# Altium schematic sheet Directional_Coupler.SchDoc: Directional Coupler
size A4; Author: Almela; Revision: 1.2; SheetNumber: 6; SheetTotal: 7
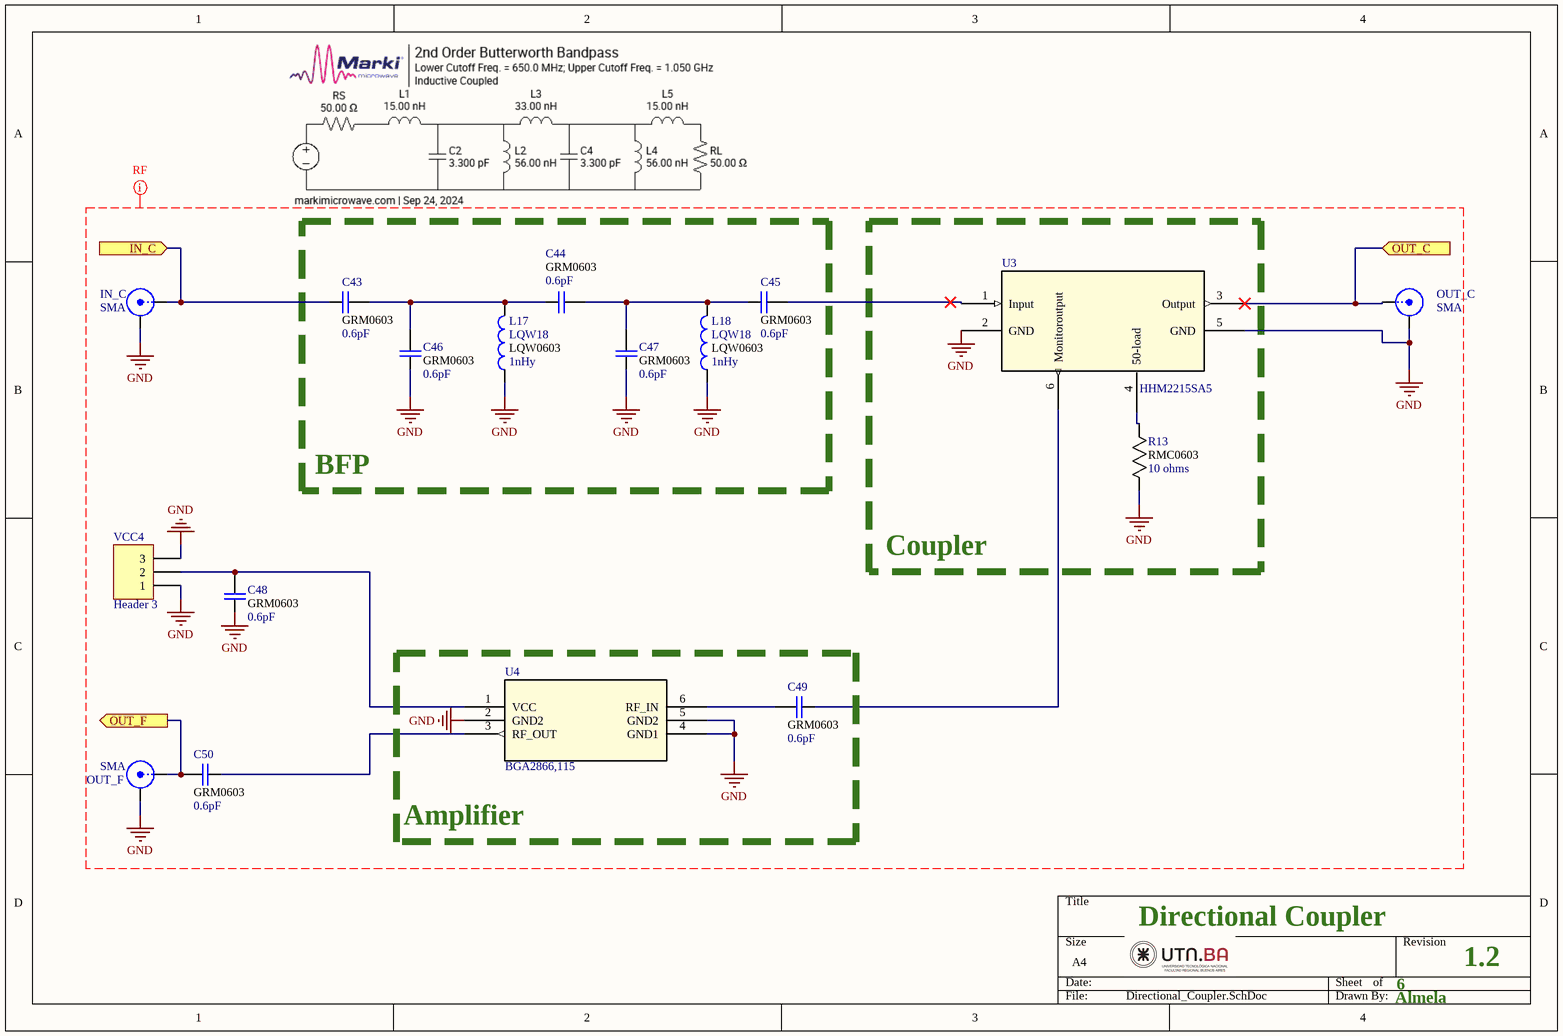
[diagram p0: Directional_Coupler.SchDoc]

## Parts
C43  value 0.6pF  footprint: GRM0603  [CAPC1608X90N]  (hidden comment: Cap 0603)
C44  value 0.6pF  footprint: GRM0603  [CAPC1608X90N]  (hidden comment: Cap 0603)
C45  value 0.6pF  footprint: GRM0603  [CAPC1608X90N]  (hidden comment: Cap 0603)
C46  value 0.6pF  footprint: GRM0603  [CAPC1608X90N]  (hidden comment: Cap 0603)
C47  value 0.6pF  footprint: GRM0603  [CAPC1608X90N]  (hidden comment: Cap 0603)
C48  value 0.6pF  footprint: GRM0603  [CAPC1608X90N]  (hidden comment: Cap 0603)
C49  value 0.6pF  footprint: GRM0603  [CAPC1608X90N]  (hidden comment: Cap 0603)
C50  value 0.6pF  footprint: GRM0603  [CAPC1608X90N]  (hidden comment: Cap 0603)
IN_C  SMA  [SMA-142-0701-851_V2]
L17  LQW18  value 1nHy  Parameter 1: LQW0603  [INDC1608X100N]
L18  LQW18  value 1nHy  Parameter 1: LQW0603  [INDC1608X100N]
OUT_C  SMA  [SMA-142-0701-851_V2]
OUT_F  SMA  [SMA-142-0701-851]
R13  value 10 ohms  footprint: RMC0603  [RESC1508X55N]  (hidden comment: Resistor)
U3  HHM2215SA5  [HHM-6_1P6X0P8]
U4  BGA2866,115  [SOT363_NXP]
VCC4  Header 3  [HDR1X3]

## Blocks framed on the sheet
BFP: C43-C47 L17 L18
Coupler: R13 U3
Amplifier: C49 U4

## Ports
IN_C (in), OUT_C (in), OUT_F (out)

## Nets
GND: C46.1 C47.1 C48.1 IN_C.2(Y) L17.1 L18.1 OUT_C.2(Y) OUT_F.2(Y) R13.1 U3.2(GND) U3.5(GND) U4.2(GND2) U4.4(GND1) U4.5(GND2) VCC4.1 VCC4.3
IN_C: C43.1 IN_C.1(X) ; port IN_C
OUT_C: OUT_C.1(X) U3.3(Output) ; port OUT_C
OUT_F: C50.2 OUT_F.1(X) ; port OUT_F
NetC43_2: C43.2 C44.1 C46.2 L17.2
NetC44_2: C44.2 C45.1 C47.2 L18.2
NetC45_2: C45.2 U3.1(Input)
NetC48_2: C48.2 U4.1(VCC) VCC4.2
NetC49_1: C49.1 U3.6(Monitoroutput)
NetC49_2: C49.2 U4.6(RF_IN)
NetC50_1: C50.1 U4.3(RF_OUT)
NetR13_2: R13.2 U3.4(50-load)

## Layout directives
net class RF50R: GND

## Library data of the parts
C43-C50 = Cap: Capacitor GRM18 0603
IN_C OUT_C = SMA: SMA Straight Connector
L17 L18 = LQW18: Ind RF Chip Wirewound 18nH 5% 100MHz 40Q-Factor 550mA 0603 Paper T/R; MP: LQW18AN18NJ00D
OUT_F = SMB: SMB Straight Connector
R13 = Resistor: Resistor RMC0603; Mfr_Name: Stackpole International
U3 = HHM2215SA5: No Description Available; Mfr_Name: TDK
U4 = BGA2866,115: No Description Available; Mfr_Name: NXP
VCC4 = Header 3: Header, 3-Pin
